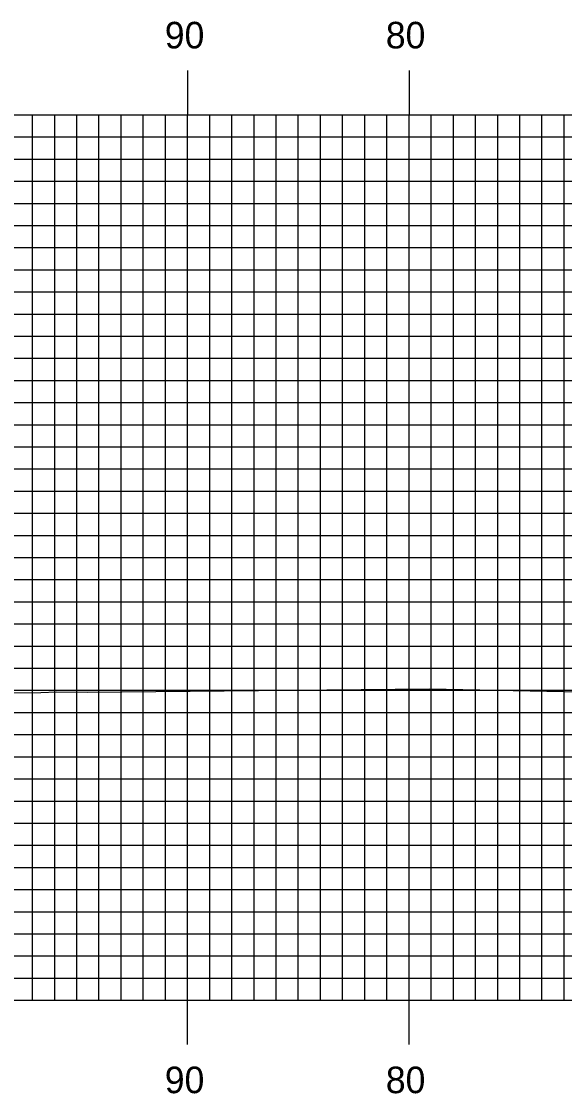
# Model space of a CAD drawing. Extents: x 1812948 to 1813291, y 442591 to 442811.
# Drawn here: x 1813015.96 to 1813040.47, y 442664.45 to 442712.88 of the extents above; entities that cross this region are included whole.
import ezdxf

# ---------------------------------------------------------------- set-up
doc = ezdxf.new("R2010")
doc.units = 0
for name, color, linetype in [('H_V ANNOTATION', 7, 'Continuous'), ('MAJOR', 7, 'Continuous'), ('MINOR', 7, 'Continuous'), ('S_Roadway_Centerline', 7, 'Continuous')]:
    doc.layers.add(name, color=color, linetype=linetype)

msp = doc.modelspace()

# ---------------------------------------------------------------- linework, layer by layer
at = {"layer": 'MAJOR'}
for p, q in [((1813023.455, 442710.669), (1813023.455, 442708.665)), ((1813033.455, 442710.669), (1813033.455, 442708.665)), ((1812973.455, 442708.665), (1813253.455, 442708.665)), ((1812973.455, 442708.665), (1813253.455, 442708.665)), ((1813023.455, 442668.665), (1813023.455, 442708.665)), ((1813033.455, 442668.665), (1813033.455, 442708.665)), ((1812973.455, 442703.665), (1813253.455, 442703.665)), ((1812973.455, 442698.665), (1813253.455, 442698.665)), ((1812973.455, 442693.665), (1813253.455, 442693.665)), ((1812973.455, 442688.665), (1813253.455, 442688.665)), ((1812973.455, 442683.665), (1813253.455, 442683.665)), ((1812973.455, 442678.665), (1813253.455, 442678.665)), ((1812973.455, 442673.665), (1813253.455, 442673.665)), ((1812973.455, 442668.665), (1813253.455, 442668.665)), ((1812973.455, 442668.665), (1813253.455, 442668.665)), ((1813023.455, 442666.661), (1813023.455, 442668.665)), ((1813033.455, 442666.661), (1813033.455, 442668.665))]:
    msp.add_line(p, q, dxfattribs=at)
at = {"layer": 'MINOR'}
for p, q in [((1813016.455, 442668.665), (1813016.455, 442708.665)), ((1813017.455, 442668.665), (1813017.455, 442708.665)), ((1813018.455, 442668.665), (1813018.455, 442708.665)), ((1813019.455, 442668.665), (1813019.455, 442708.665)), ((1813020.455, 442668.665), (1813020.455, 442708.665)), ((1813021.455, 442668.665), (1813021.455, 442708.665)), ((1813022.455, 442668.665), (1813022.455, 442708.665)), ((1813024.455, 442668.665), (1813024.455, 442708.665)), ((1813025.455, 442668.665), (1813025.455, 442708.665)), ((1813026.455, 442668.665), (1813026.455, 442708.665)), ((1813027.455, 442668.665), (1813027.455, 442708.665)), ((1813028.455, 442668.665), (1813028.455, 442708.665)), ((1813029.455, 442668.665), (1813029.455, 442708.665)), ((1813030.455, 442668.665), (1813030.455, 442708.665)), ((1813031.455, 442668.665), (1813031.455, 442708.665)), ((1813032.455, 442668.665), (1813032.455, 442708.665)), ((1813034.455, 442668.665), (1813034.455, 442708.665)), ((1813035.455, 442668.665), (1813035.455, 442708.665)), ((1813036.455, 442668.665), (1813036.455, 442708.665)), ((1813037.455, 442668.665), (1813037.455, 442708.665)), ((1813038.455, 442668.665), (1813038.455, 442708.665)), ((1813039.455, 442668.665), (1813039.455, 442708.665)), ((1813040.455, 442668.665), (1813040.455, 442708.665)), ((1812973.455, 442707.665), (1813253.455, 442707.665)), ((1812973.455, 442706.665), (1813253.455, 442706.665)), ((1812973.455, 442705.665), (1813253.455, 442705.665)), ((1812973.455, 442704.665), (1813253.455, 442704.665)), ((1812973.455, 442702.665), (1813253.455, 442702.665)), ((1812973.455, 442701.665), (1813253.455, 442701.665)), ((1812973.455, 442700.665), (1813253.455, 442700.665)), ((1812973.455, 442699.665), (1813253.455, 442699.665)), ((1812973.455, 442697.665), (1813253.455, 442697.665)), ((1812973.455, 442696.665), (1813253.455, 442696.665)), ((1812973.455, 442695.665), (1813253.455, 442695.665)), ((1812973.455, 442694.665), (1813253.455, 442694.665)), ((1812973.455, 442692.665), (1813253.455, 442692.665)), ((1812973.455, 442691.665), (1813253.455, 442691.665)), ((1812973.455, 442690.665), (1813253.455, 442690.665)), ((1812973.455, 442689.665), (1813253.455, 442689.665)), ((1812973.455, 442687.665), (1813253.455, 442687.665)), ((1812973.455, 442686.665), (1813253.455, 442686.665)), ((1812973.455, 442685.665), (1813253.455, 442685.665)), ((1812973.455, 442684.665), (1813253.455, 442684.665)), ((1812973.455, 442682.665), (1813253.455, 442682.665)), ((1812973.455, 442681.665), (1813253.455, 442681.665)), ((1812973.455, 442680.665), (1813253.455, 442680.665)), ((1812973.455, 442679.665), (1813253.455, 442679.665)), ((1812973.455, 442677.665), (1813253.455, 442677.665)), ((1812973.455, 442676.665), (1813253.455, 442676.665)), ((1812973.455, 442675.665), (1813253.455, 442675.665)), ((1812973.455, 442674.665), (1813253.455, 442674.665)), ((1812973.455, 442672.665), (1813253.455, 442672.665)), ((1812973.455, 442671.665), (1813253.455, 442671.665)), ((1812973.455, 442670.665), (1813253.455, 442670.665)), ((1812973.455, 442669.665), (1813253.455, 442669.665))]:
    msp.add_line(p, q, dxfattribs=at)
at = {"layer": 'S_Roadway_Centerline'}
msp.add_lwpolyline([(1813001.063, 442682.558), (1813016.823, 442682.571), (1813017.532, 442682.594), (1813018.938, 442682.579), (1813034.384, 442682.727), (1813040.431, 442682.613), (1813050.766, 442682.533)], dxfattribs=at)

# ---------------------------------------------------------------- texts
at = {"layer": 'H_V ANNOTATION'}
for s, p in [('90', (1813022.427, 442711.665)), ('80', (1813032.406, 442711.665)), ('90', (1813022.427, 442664.465)), ('80', (1813032.406, 442664.465))]:
    msp.add_text(s, height=1.2, dxfattribs=at).set_placement(p)

doc.saveas('drawing.dxf')
